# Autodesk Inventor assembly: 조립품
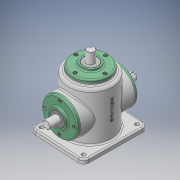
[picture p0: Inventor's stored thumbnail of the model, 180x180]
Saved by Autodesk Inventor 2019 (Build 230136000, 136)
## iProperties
Created: 2020-12
Part Number: 조립품
Material: 일반
Document SubType Name: Assembly
Designer: jun-1-7
Author: jun-1-7
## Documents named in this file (16)
- C:\Users\jun-1-7\Desktop\701207V1008\조립품.iam
- C:\Users\jun-1-7\Desktop\701207V1008\본체.ipt
- C:\Users\jun-1-7\Desktop\701207V1008\메인 베벨기어.ipt
- C:\Users\jun-1-7\Desktop\701207V1008\메인 축.ipt
- 메인 축.ipt
- C:\Users\jun-1-7\Desktop\701207V1008\베어링 6203.ipt
- C:\Users\jun-1-7\Desktop\701207V1008\볼트 M4.ipt
- 볼트 M4.ipt
- C:\Users\jun-1-7\Desktop\701207V1008\서브 베벨기어.ipt
- C:\Users\jun-1-7\Desktop\701207V1008\서브 축.ipt
- 서브 축.ipt
- C:\Users\jun-1-7\Desktop\701207V1008\오일 실.ipt
- 오일 실.ipt
- C:\Users\jun-1-7\Desktop\701207V1008\커버.ipt
- C:\Users\jun-1-7\Desktop\701207V1008\키 4x4.ipt
- C:\Users\jun-1-7\Desktop\701207V1008\키 5x5.ipt
